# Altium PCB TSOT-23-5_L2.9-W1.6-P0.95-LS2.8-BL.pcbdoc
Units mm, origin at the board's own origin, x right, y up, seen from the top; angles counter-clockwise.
Board outline 16.07 x 16.12 mm, 2 copper layers (Top Layer, Bottom Layer), stack 0 mm thick; 1 components, 0 nets, 5 pads, 0 vias.
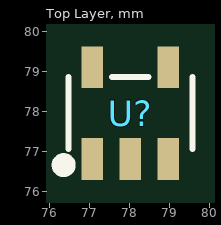
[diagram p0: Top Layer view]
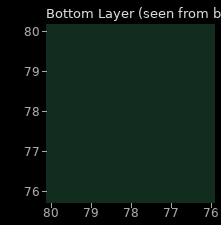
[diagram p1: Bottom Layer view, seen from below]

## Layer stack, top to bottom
Top Layer: signal copper (thickness not stored)
Bottom Layer: signal copper (thickness not stored)

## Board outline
85.92,69.85 69.85,69.85 69.85,85.971 85.92,85.971

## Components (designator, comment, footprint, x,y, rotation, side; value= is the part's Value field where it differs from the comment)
U? "" TSOT-23-5_L2.9-W1.6-P0.95-LS2.8-BL 78.018,77.951 r0 top

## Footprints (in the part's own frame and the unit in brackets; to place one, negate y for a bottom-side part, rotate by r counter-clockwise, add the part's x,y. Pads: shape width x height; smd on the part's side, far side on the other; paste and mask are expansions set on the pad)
TSOT-23-5_L2.9-W1.6-P0.95-LS2.8-BL [mm]
  rect 0.532x1.045 smd: 1(-0.95,-1.148) 2(0,-1.148) 3(0.95,-1.148) 4(0.95,1.148) 5(-0.95,1.148)
  silkscreen extent -1.82,-1.45 1.55,0.9

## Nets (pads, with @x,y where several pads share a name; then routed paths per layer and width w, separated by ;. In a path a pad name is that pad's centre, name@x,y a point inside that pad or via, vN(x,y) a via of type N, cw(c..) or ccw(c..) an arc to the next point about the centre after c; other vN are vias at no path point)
pads on no net: U?.1 U?.2 U?.3 U?.4 U?.5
